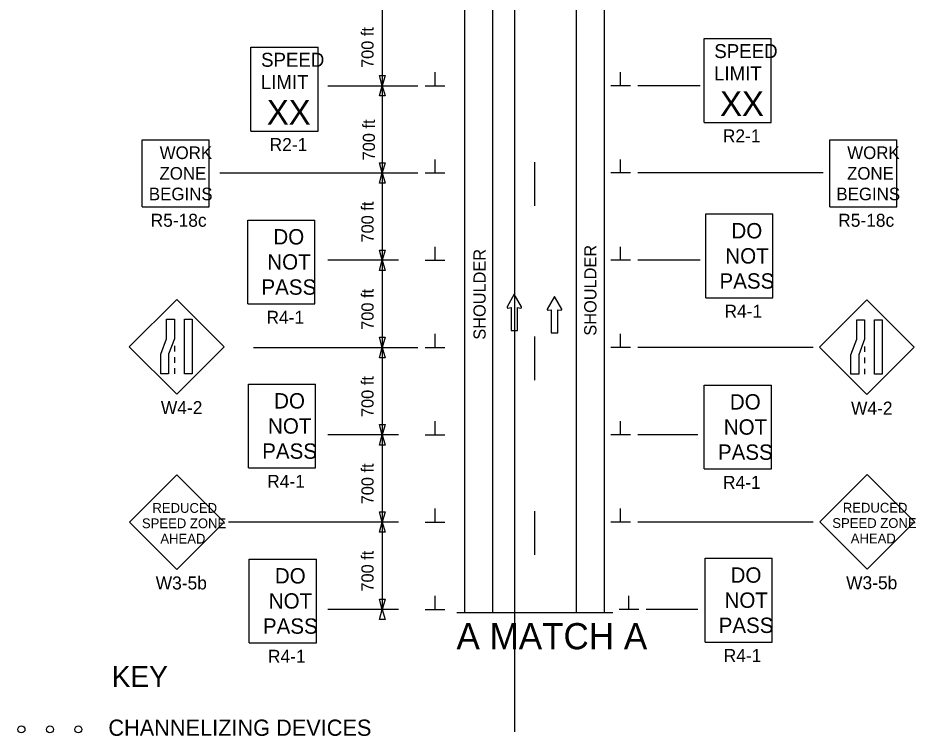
# Model space of a CAD drawing. Extents: x 15277 to 18126, y 1908 to 6555.
# Drawn here: x 15297 to 15812, y 2406 to 2818 of the extents above; entities that cross this region are included whole.
import ezdxf

# ---------------------------------------------------------------- set-up
doc = ezdxf.new("R2010")
doc.units = 0
for name, color, linetype in [('ALI_LEGAL_EX', 7, 'Continuous'), ('MT_SCRATCH_LEVEL_E', 7, 'Continuous'), ('PAVT_EDGE_EX', 7, 'Continuous'), ('TRAFFIC_SIGNS_PR', 7, 'Continuous'), ('TYPICAL_TEXT_DIMEN_EX', 7, 'Continuous'), ('TYPICAL_TEXT_DIMEN_PR', 7, 'Continuous')]:
    doc.layers.add(name, color=color, linetype=linetype)

msp = doc.modelspace()

# ---------------------------------------------------------------- linework, layer by layer
at = {"layer": 'ALI_LEGAL_EX'}
msp.add_line((15581.68, 3237.79), (15581.68, 2408.6), dxfattribs=at)
for points in [[(15593, 2735), (15593, 2710)], [(15593, 2635), (15593, 2610)], [(15593, 2535), (15593, 2510)]]:
    msp.add_lwpolyline(points, dxfattribs=at)
at = {"layer": 'MT_SCRATCH_LEVEL_E'}
for p, q in [((15581.51, 2659.29), (15577.39, 2652.05)), ((15585.65, 2652.05), (15581.51, 2659.29)), ((15604.48, 2658.02), (15600.37, 2650.78)), ((15608.63, 2650.78), (15604.48, 2658.02)), ((15577.88, 2651.37), (15579.65, 2651.68)), ((15579.65, 2651.68), (15579.65, 2638.43)), ((15583.4, 2638.43), (15583.4, 2651.68)), ((15583.4, 2651.68), (15585.17, 2651.37)), ((15600.85, 2650.1), (15602.63, 2650.41)), ((15602.63, 2650.41), (15602.63, 2637.16)), ((15606.37, 2637.16), (15606.37, 2650.41)), ((15606.37, 2650.41), (15608.15, 2650.1)), ((15579.65, 2638.43), (15583.4, 2638.43)), ((15602.63, 2637.16), (15606.37, 2637.16))]:
    msp.add_line(p, q, dxfattribs=at)
for centre, start, end in [((15577.8, 2651.83), 150.4248, 279.9638), ((15585.24, 2651.83), 260.0362, 29.7731), ((15600.78, 2650.56), 150.4248, 279.9638), ((15608.22, 2650.56), 260.0362, 29.7731)]:
    msp.add_arc(centre, 0.463, start, end, dxfattribs=at)
at = {"layer": 'PAVT_EDGE_EX'}
for p, q in [((15633, 3163.21), (15633, 2476.81)), ((15553, 3162.29), (15553, 2476.81)), ((15569, 3162.29), (15569, 2476.81)), ((15617, 3162.29), (15617, 2476.81))]:
    msp.add_line(p, q, dxfattribs=at)
at = {"layer": 'TRAFFIC_SIGNS_PR'}
for p, q in [((15690.24, 2805.71), (15728.64, 2805.71)), ((15690.24, 2757.71), (15690.24, 2805.71)), ((15728.64, 2757.71), (15728.64, 2805.71)), ((15430.69, 2800.74), (15469.09, 2800.74)), ((15430.69, 2752.74), (15430.69, 2800.74)), ((15469.09, 2752.74), (15469.09, 2800.74)), ((15690.24, 2757.71), (15728.64, 2757.71)), ((15430.69, 2752.74), (15469.09, 2752.74)), ((15368.42, 2709.37), (15368.42, 2747.77)), ((15368.42, 2747.77), (15406.82, 2747.77)), ((15406.82, 2709.37), (15406.82, 2747.77)), ((15762.16, 2709.37), (15762.16, 2747.77)), ((15762.16, 2747.77), (15800.56, 2747.77)), ((15800.56, 2709.37), (15800.56, 2747.77)), ((15368.42, 2709.37), (15406.82, 2709.37)), ((15691.19, 2657.26), (15691.19, 2705.26)), ((15691.19, 2705.26), (15729.59, 2705.26)), ((15729.59, 2657.26), (15729.59, 2705.26)), ((15762.16, 2709.37), (15800.56, 2709.37)), ((15428.89, 2653.79), (15428.89, 2701.79)), ((15428.89, 2701.79), (15467.29, 2701.79)), ((15467.29, 2653.79), (15467.29, 2701.79)), ((15388.15, 2656.34), (15361, 2629.18)), ((15415.31, 2629.18), (15388.15, 2656.34)), ((15428.89, 2653.79), (15467.29, 2653.79)), ((15691.19, 2657.26), (15729.59, 2657.26)), ((15783.35, 2656.05), (15756.2, 2628.9)), ((15810.5, 2628.9), (15783.35, 2656.05)), ((15361, 2629.18), (15388.15, 2602.03)), ((15386.91, 2629.67), (15386.91, 2626.47)), ((15388.15, 2602.03), (15415.31, 2629.18)), ((15756.2, 2628.9), (15783.35, 2601.75)), ((15782.1, 2629.39), (15782.1, 2626.19)), ((15783.35, 2601.75), (15810.5, 2628.9)), ((15386.91, 2623.27), (15386.91, 2620.07)), ((15782.1, 2622.99), (15782.1, 2619.79)), ((15386.91, 2616.87), (15386.91, 2613.67)), ((15782.1, 2616.59), (15782.1, 2613.39)), ((15429.32, 2559.8), (15429.32, 2607.8)), ((15429.32, 2607.8), (15467.72, 2607.8)), ((15467.72, 2559.8), (15467.72, 2607.8)), ((15690.3, 2559.21), (15690.3, 2607.21)), ((15690.3, 2607.21), (15728.7, 2607.21)), ((15728.7, 2559.21), (15728.7, 2607.21)), ((15429.32, 2559.8), (15467.72, 2559.8)), ((15690.3, 2559.21), (15728.7, 2559.21)), ((15783.55, 2556.03), (15756.4, 2528.88)), ((15810.71, 2528.88), (15783.55, 2556.03)), ((15388.2, 2555.88), (15361.05, 2528.72)), ((15415.35, 2528.72), (15388.2, 2555.88)), ((15361.05, 2528.72), (15388.2, 2501.57)), ((15388.2, 2501.57), (15415.35, 2528.72)), ((15756.4, 2528.88), (15783.55, 2501.72)), ((15783.55, 2501.72), (15810.71, 2528.88)), ((15429.74, 2459.55), (15429.74, 2507.55)), ((15429.74, 2507.55), (15468.14, 2507.55)), ((15468.14, 2459.55), (15468.14, 2507.55)), ((15690.72, 2460), (15690.72, 2508)), ((15690.72, 2508), (15729.12, 2508)), ((15729.12, 2460), (15729.12, 2508)), ((15429.74, 2459.55), (15468.14, 2459.55)), ((15690.72, 2460), (15729.12, 2460))]:
    msp.add_line(p, q, dxfattribs=at)
for points in [[(15386.91, 2644.92), (15386.91, 2633.74), (15383.56, 2624.86), (15383.56, 2613.67), (15379.07, 2613.67), (15379.07, 2624.86), (15382.41, 2633.74), (15382.41, 2644.92)], [(15397.04, 2644.92), (15397.04, 2613.67), (15392.55, 2613.67), (15392.55, 2644.92)], [(15782.1, 2644.64), (15782.1, 2633.46), (15778.76, 2624.57), (15778.76, 2613.39), (15774.26, 2613.39), (15774.26, 2624.57), (15777.61, 2633.46), (15777.61, 2644.64)], [(15792.24, 2644.64), (15792.24, 2613.39), (15787.74, 2613.39), (15787.74, 2644.64)]]:
    msp.add_lwpolyline(points, close=True, dxfattribs=at)
for centre in [(15299.26, 2409.95), (15315.56, 2409.95), (15331.86, 2409.95)]:
    msp.add_circle(centre, 2, dxfattribs=at)
at = {"layer": 'TYPICAL_TEXT_DIMEN_PR'}
for p, q in [((15505.88, 2828.74), (15505.88, 2778.74)), ((15505.88, 2778.74), (15504.31, 2784.61)), ((15504.31, 2784.61), (15505.88, 2784.61)), ((15505.88, 2784.61), (15507.45, 2784.61)), ((15507.45, 2784.61), (15505.88, 2778.74)), ((15536.12, 2778.74), (15536.12, 2786.53)), ((15642.37, 2778.74), (15642.37, 2786.53)), ((15474.73, 2778.74), (15526.25, 2778.74)), ((15504.31, 2772.88), (15505.88, 2778.74)), ((15504.31, 2772.88), (15505.88, 2778.74)), ((15505.88, 2778.74), (15505.88, 2728.74)), ((15505.88, 2778.74), (15507.45, 2772.88)), ((15505.88, 2778.74), (15507.45, 2772.88)), ((15530.5, 2778.74), (15541.75, 2778.74)), ((15648, 2778.74), (15636.75, 2778.74)), ((15687.92, 2778.74), (15652.25, 2778.74)), ((15505.88, 2772.88), (15504.31, 2772.88)), ((15505.88, 2772.88), (15504.31, 2772.88)), ((15507.45, 2772.88), (15505.88, 2772.88)), ((15507.45, 2772.88), (15505.88, 2772.88)), ((15536.12, 2728.74), (15536.12, 2736.53)), ((15642.37, 2728.74), (15642.37, 2736.53)), ((15505.88, 2728.74), (15504.31, 2734.61)), ((15504.31, 2734.61), (15505.88, 2734.61)), ((15505.88, 2728.74), (15504.31, 2734.61)), ((15504.31, 2734.61), (15505.88, 2734.61)), ((15505.88, 2734.61), (15507.45, 2734.61)), ((15507.45, 2734.61), (15505.88, 2728.74)), ((15505.88, 2734.61), (15507.45, 2734.61)), ((15507.45, 2734.61), (15505.88, 2728.74)), ((15412.92, 2728.74), (15526.25, 2728.74)), ((15504.31, 2722.88), (15505.88, 2728.74)), ((15505.88, 2728.74), (15505.88, 2678.74)), ((15505.88, 2728.74), (15507.45, 2722.88)), ((15530.5, 2728.74), (15541.75, 2728.74)), ((15648, 2728.74), (15636.75, 2728.74)), ((15758.46, 2728.74), (15652.25, 2728.74)), ((15505.88, 2722.88), (15504.31, 2722.88)), ((15507.45, 2722.88), (15505.88, 2722.88)), ((15505.88, 2678.74), (15504.31, 2684.61)), ((15504.31, 2684.61), (15505.88, 2684.61)), ((15505.88, 2684.61), (15507.45, 2684.61)), ((15507.45, 2684.61), (15505.88, 2678.74)), ((15536.12, 2678.74), (15536.12, 2686.53)), ((15642.37, 2678.74), (15642.37, 2686.53)), ((15515.11, 2678.74), (15474.73, 2678.74)), ((15504.31, 2672.88), (15505.88, 2678.74)), ((15505.88, 2678.74), (15505.88, 2628.74)), ((15505.88, 2678.74), (15507.45, 2672.88)), ((15530.5, 2678.74), (15541.75, 2678.74)), ((15648, 2678.74), (15636.75, 2678.74)), ((15687.92, 2678.74), (15652.25, 2678.74)), ((15505.88, 2672.88), (15504.31, 2672.88)), ((15507.45, 2672.88), (15505.88, 2672.88)), ((15505.88, 2628.74), (15504.31, 2634.61)), ((15504.31, 2634.61), (15505.88, 2634.61)), ((15505.88, 2628.74), (15504.31, 2634.61)), ((15504.31, 2634.61), (15505.88, 2634.61)), ((15505.88, 2634.61), (15507.45, 2634.61)), ((15507.45, 2634.61), (15505.88, 2628.74)), ((15505.88, 2634.61), (15507.45, 2634.61)), ((15507.45, 2634.61), (15505.88, 2628.74)), ((15536.12, 2628.74), (15536.12, 2636.53)), ((15642.37, 2628.74), (15642.37, 2636.53)), ((15432.15, 2628.74), (15526.25, 2628.74)), ((15504.31, 2622.88), (15505.88, 2628.74)), ((15505.88, 2628.74), (15505.88, 2578.74)), ((15505.88, 2628.74), (15507.45, 2622.88)), ((15530.5, 2628.74), (15541.75, 2628.74)), ((15648, 2628.74), (15636.75, 2628.74)), ((15752.65, 2628.74), (15652.25, 2628.74)), ((15505.88, 2622.88), (15504.31, 2622.88)), ((15507.45, 2622.88), (15505.88, 2622.88)), ((15505.88, 2578.74), (15504.31, 2584.61)), ((15504.31, 2584.61), (15505.88, 2584.61)), ((15505.88, 2584.61), (15507.45, 2584.61)), ((15507.45, 2584.61), (15505.88, 2578.74)), ((15536.12, 2578.74), (15536.12, 2586.53)), ((15642.37, 2578.74), (15642.37, 2586.53)), ((15515.11, 2578.74), (15474.73, 2578.74)), ((15504.31, 2572.88), (15505.88, 2578.74)), ((15505.88, 2578.74), (15507.45, 2572.88)), ((15505.88, 2578.74), (15505.88, 2528.74)), ((15530.5, 2578.74), (15541.75, 2578.74)), ((15648, 2578.74), (15636.75, 2578.74)), ((15686.6, 2578.74), (15652.25, 2578.74)), ((15505.88, 2572.88), (15504.31, 2572.88)), ((15507.45, 2572.88), (15505.88, 2572.88)), ((15536.12, 2528.74), (15536.12, 2536.53)), ((15642.37, 2528.74), (15642.37, 2536.53)), ((15505.88, 2528.74), (15504.31, 2534.61)), ((15504.31, 2534.61), (15505.88, 2534.61)), ((15505.88, 2534.61), (15507.45, 2534.61)), ((15507.45, 2534.61), (15505.88, 2528.74)), ((15515.11, 2528.74), (15417.81, 2528.74)), ((15504.31, 2522.88), (15505.88, 2528.74)), ((15505.88, 2528.74), (15507.45, 2522.88)), ((15505.88, 2528.74), (15505.88, 2478.74)), ((15530.5, 2528.74), (15541.75, 2528.74)), ((15648, 2528.74), (15636.75, 2528.74)), ((15752.65, 2528.74), (15652.25, 2528.74)), ((15505.88, 2522.88), (15504.31, 2522.88)), ((15507.45, 2522.88), (15505.88, 2522.88)), ((15505.88, 2478.74), (15504.31, 2484.61)), ((15504.31, 2484.61), (15505.88, 2484.61)), ((15505.88, 2484.61), (15507.45, 2484.61)), ((15507.45, 2484.61), (15505.88, 2478.74)), ((15536.12, 2478.74), (15536.12, 2486.53)), ((15647.13, 2478.74), (15647.13, 2486.53)), ((15515.11, 2478.74), (15474.73, 2478.74)), ((15504.31, 2472.88), (15505.88, 2478.74)), ((15505.88, 2478.74), (15507.45, 2472.88)), ((15530.5, 2478.74), (15541.75, 2478.74)), ((15637.95, 2476.81), (15548.53, 2476.81)), ((15652.75, 2478.74), (15641.5, 2478.74)), ((15686.6, 2478.74), (15657.07, 2478.74)), ((15505.88, 2472.88), (15504.31, 2472.88)), ((15507.45, 2472.88), (15505.88, 2472.88))]:
    msp.add_line(p, q, dxfattribs=at)

# ---------------------------------------------------------------- texts
at = {"layer": 'TRAFFIC_SIGNS_PR'}
for s, height, p in [('SPEED', 8, (15696.01, 2794.58)), ('SPEED', 8, (15436.46, 2789.6)), ('LIMIT', 8, (15695.85, 2781.78)), ('LIMIT', 8, (15436.3, 2776.8)), ('XX', 14.031, (15699.36, 2761.47)), ('XX', 14.031, (15439.8, 2756.5)), ('R2-1', 7.44, (15700.92, 2746.27)), ('R2-1', 7.44, (15441.37, 2741.3)), ('WORK', 7.217, (15378.42, 2736.74)), ('WORK', 7.217, (15772.16, 2736.74)), ('ZONE', 7.217, (15378.3, 2724.93)), ('ZONE', 7.217, (15772.04, 2724.93)), ('BEGINS', 7.217, (15372.23, 2713.12)), ('BEGINS', 7.217, (15765.97, 2713.12)), ('R5-18c', 7.44, (15373.23, 2697.93)), ('R5-18c', 7.44, (15766.97, 2697.93)), ('DO', 8.8, (15705.83, 2691.27)), ('DO', 8.8, (15443.52, 2687.79)), ('NOT', 8.8, (15702.34, 2676.87)), ('NOT', 8.8, (15440.04, 2673.39)), ('PASS', 8.8, (15698.99, 2662.47)), ('PASS', 8.8, (15436.69, 2658.99)), ('R4-1', 7.44, (15439.57, 2642.35)), ('R4-1', 7.44, (15701.87, 2645.83)), ('DO', 8.8, (15443.95, 2593.8)), ('W4-2', 7.44, (15379.11, 2590.59)), ('DO', 8.8, (15704.94, 2593.21)), ('W4-2', 7.44, (15774.31, 2590.31)), ('NOT', 8.8, (15440.46, 2579.4)), ('NOT', 8.8, (15701.45, 2578.81)), ('PASS', 8.8, (15437.11, 2565)), ('PASS', 8.8, (15698.1, 2564.41)), ('R4-1', 7.44, (15439.99, 2548.36)), ('R4-1', 7.44, (15700.98, 2547.77)), ('REDUCED', 5.6, (15374.26, 2534.03)), ('REDUCED', 5.6, (15769.61, 2534.18)), ('SPEED ZONE', 5.6, (15368.25, 2525.23)), ('SPEED ZONE', 5.6, (15763.6, 2525.38)), ('AHEAD', 5.6, (15378.81, 2516.43)), ('AHEAD', 5.6, (15774.16, 2516.58)), ('DO', 8.8, (15444.37, 2493.55)), ('DO', 8.8, (15705.35, 2494)), ('W3-5b', 7.44, (15376.15, 2490.13)), ('W3-5b', 7.44, (15771.51, 2490.28)), ('NOT', 8.8, (15440.88, 2479.15)), ('NOT', 8.8, (15701.87, 2479.6)), ('PASS', 8.8, (15698.52, 2465.2)), ('PASS', 8.8, (15437.53, 2464.75)), ('R4-1', 7.44, (15440.41, 2448.11)), ('R4-1', 7.44, (15701.4, 2448.56))]:
    msp.add_text(s, height=height, dxfattribs=at).set_placement(p)
at = {"layer": 'TYPICAL_TEXT_DIMEN_EX'}
for s, height, p in [('KEY', 12, (15350.98, 2434.19)), ('CHANNELIZING DEVICES', 9.3, (15349.03, 2406.28))]:
    msp.add_text(s, height=height, dxfattribs=at).set_placement(p)
at = {"layer": 'TYPICAL_TEXT_DIMEN_PR'}
for s, p in [('700 ft', (15500.92, 2788.91)), ('700 ft', (15501.7, 2735.97)), ('700 ft', (15500.92, 2688.91)), ('SHOULDER', (15565.1, 2633.23)), ('SHOULDER', (15628.53, 2635.54)), ('700 ft', (15500.92, 2638.91)), ('700 ft', (15500.92, 2588.91)), ('700 ft', (15500.92, 2538.91)), ('700 ft', (15500.92, 2488.91))]:
    msp.add_text(s, height=7, rotation=90, dxfattribs=at).set_placement(p)
msp.add_text('A MATCH A', height=15, dxfattribs=at).set_placement((15548.39, 2455.87))

doc.saveas('drawing.dxf')
